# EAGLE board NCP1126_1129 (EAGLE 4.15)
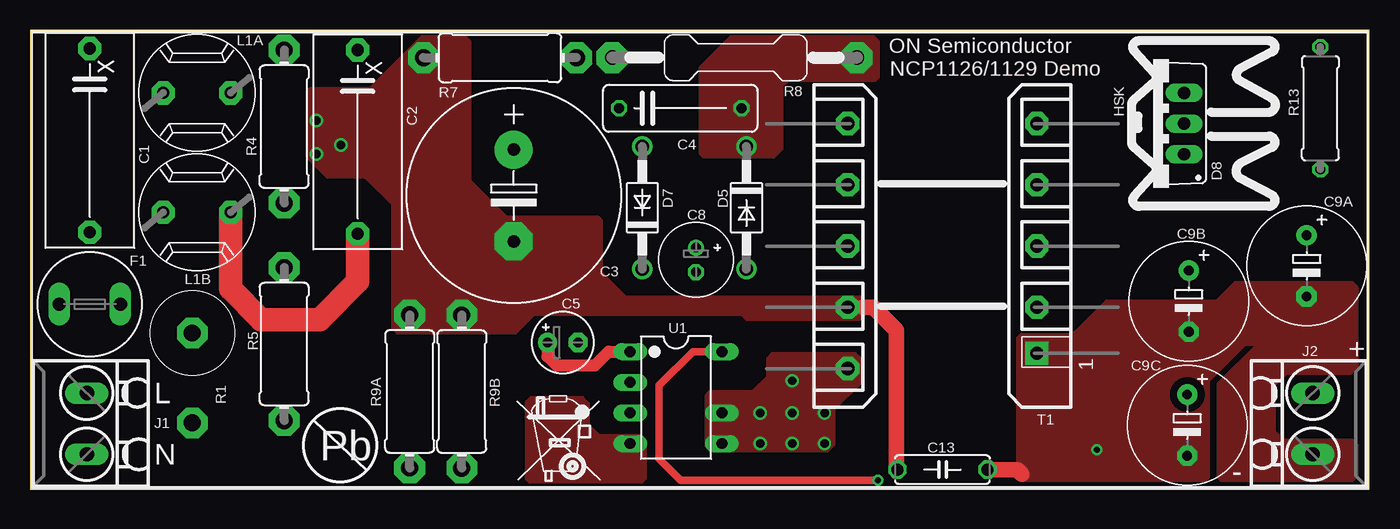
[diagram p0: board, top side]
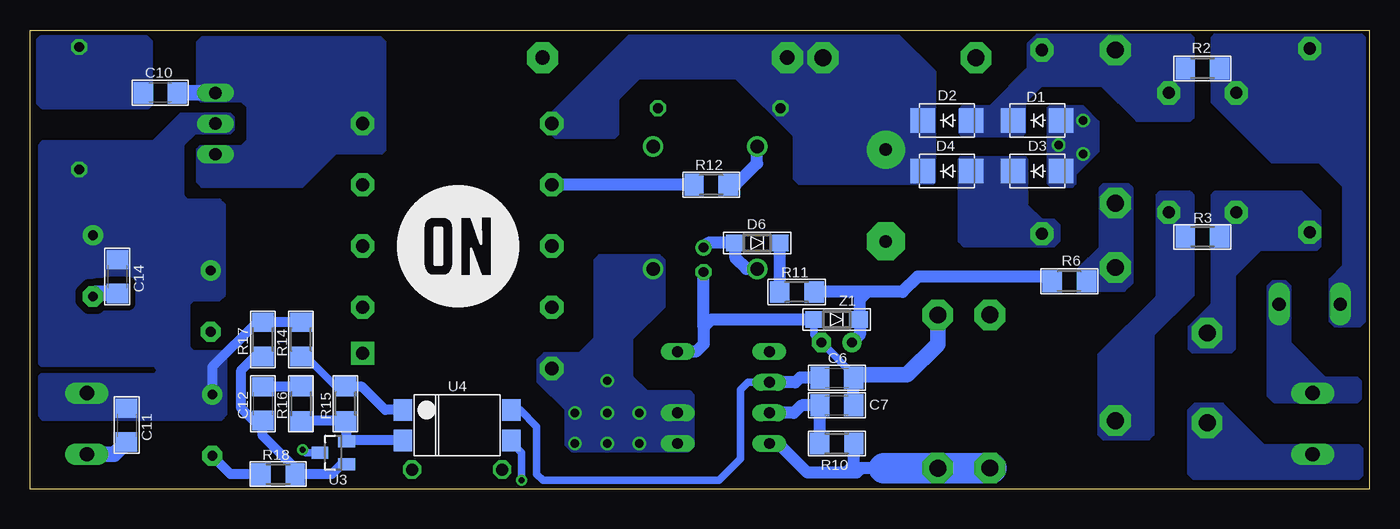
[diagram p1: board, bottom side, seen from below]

Size 111.13 x 38.1 mm. Coordinates in mm from the lower left corner, seen from the top.
Outline: 0,0 111.13,0 111.13,38.1 0,38.1 0,0
Copper layers (1*16): Top 0.035mm / dielectric 1.5mm / Bottom 0.035mm
Design rules "default": minimum track width 10mil, minimum drill 19mil, track to track 8mil, track to pad 8mil, pad to pad 8mil, via to via 8mil, smd to smd 8mil, copper to edge 10mil, drill to drill 8mil, minimum pad ring 10mil, minimum via ring 8mil, stop-mask expansion 4mil, vias tented up to drill 0mil, thermal gap 10mil

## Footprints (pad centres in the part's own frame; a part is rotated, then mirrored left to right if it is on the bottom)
XC18B7.5LS15 = drill 1.016 pad 1.93 octagon: 1 -7.62,0; 2 7.62,0
E7,5-18 = drill 1.016 pad 3.15 round: + -3.81,0 | drill 1.016 pad 3.15 octagon: - 3.81,0
C100-040X130 = drill 0.8 octagon: 1 -4.98,0; 2 5.18,0
E2,5-5 = drill 0.813 pad 1.6 round: + -1.27,0 | drill 0.813 pad 1.6 octagon: - 1.27,0
C1206 = smd 1.6 x 1.8: 1 -1.4,0; 2 1.4,0
E2-6.3 = drill 0.813 pad 1.27 round: + -1.016,0 | drill 0.813 pad 1.27 octagon: - 1.016,0
E5-10 = drill 0.8 pad 1.676 round: + -2.54,0 | drill 0.8 pad 1.676 octagon: - 2.54,0
C075-025X080 = drill 1 octagon: 1 -3.74,0; 2 3.74,0
SMA-DIODE = smd 2.032 x 2.032: A 1.994,0; C -1.994,0
DO41-10 = drill 1.118 round: A 5.08,0; C -5.08,0
SOD123 = smd 1.4 x 1.4: A 1.9,0; C -1.9,0
TO220ABS = drill 1.016 long: A1 -2.54,-2.54; A2 2.54,-2.54; C 0,-2.54
TR5 = drill 1.1 pad 1.778 long: 1 -2.54,0; 2 2.54,0
2-PIN = drill 1.2 long: + -2.54,0; - 2.54,0
RFB0810 = drill 1 pad 1.93 octagon: 1 -2.794,0; 2 2.794,0
3W-STAND-UP = drill 1.4 pad 2.54 octagon: P$1 3.75,0; P$2 -3.71,0
R1206 = smd 1.6 x 1.803: 1 -1.422,0; 2 1.422,0
0411/12 = drill 1.4 pad 2.54 octagon: 1 -6.35,0; 2 6.35,0
2W-DIA_4MM-LS_20MM = drill 1.2 pad 2.54 octagon: P$1 10.06,0; P$2 -10.26,0
0309/10 = drill 0.813 octagon: 1 -5.08,0; 2 5.08,0
E25/10/6-10P = drill 1.1 pad 1.93 square: 1 -8.89,-7.85 | drill 1.1 pad 1.93 octagon: 2 -5.08,-7.85; 3 0,-7.85; 4 5.08,-7.85; 5 10.16,-7.85; 6 10.16,7.85; 7 5.08,7.85; 8 0,7.85; 9 -5.08,7.85; 10 -10.16,7.85
DIP07_NO_PIN7 = drill 0.9 long: 1 -3.81,-3.81; 2 -1.27,-3.81; 3 1.27,-3.81; 4 3.81,-3.81; 5 3.81,3.81; 6 1.27,3.81; 8 -3.81,3.81
SOT-23 = smd 1 x 1.4: 1 -0.95,-1.1; 2 0.95,-1.1; 3 0,1.1
4PIN-SURFMOUNT-OPTO = smd 1.524 x 1.778: 1 4.496,-1.27; 2 4.496,1.27; 3 -4.496,1.27; 4 -4.496,-1.27

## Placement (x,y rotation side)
C1  0.1uF  [XC18B7.5LS15]  4.95,28.96 270 top
C2  0.1uF  [XC18B7.5LS15]  27.18,28.83 270 top
C3  47uF  [E7,5-18]  40.13,24.38 270 top
C4  10nF  [C100-040X130]  53.85,31.62 0 top
C5  4.7uF  [E2,5-5]  44.2,12.19 0 top
C6  1nF  [C1206]  44.2,9.27 0 bottom
C7  100pF  [C1206]  44.2,6.99 0 bottom
C8  22uF  [E2-6.3]  55.25,19.05 270 top
C9A  1000uF  [E5-10]  105.92,18.54 270 top
C9B  1000uF  [E5-10]  96.14,15.62 270 top
C9C  1000uF  [E5-10]  96.01,5.33 270 top
C10  0.1uF  [C1206]  100.33,32.89 180 bottom
C11  0.1uF  [C1206]  103.12,5.33 270 bottom
C12  0.1uF  [C1206]  91.82,7.11 270 bottom
C13  1nF  [C075-025X080]  75.69,1.65 0 top
C14  0.1uF  [C1206]  103.89,17.65 270 bottom
D1  MRA4007  [SMA-DIODE]  27.56,30.61 0 bottom
D2  MRA4007  [SMA-DIODE]  35.05,30.61 0 bottom
D3  MRA4007  [SMA-DIODE]  27.56,26.42 0 bottom
D4  MRA4007  [SMA-DIODE]  35.05,26.42 0 bottom
D5  1N4937  [DO41-10]  59.44,23.37 270 top
D6  MMSD4148A  [SOD123]  50.8,20.45 180 bottom
D7  1N4937  [DO41-10]  50.8,23.37 90 top
D8  MBR10H100CTG  [TO220ABS]  93.22,30.35 90 top
E$2  [ON2]  75.63,20.18 0 bottom
F1  2A/250Vac  [TR5]  4.95,15.37 180 top
HSK  [AAVID-576802B00000G]  99.19,30.35 90 top
J1  [2-PIN]  4.7,5.46 270 top
J2  [2-PIN]  106.43,5.46 90 top
L1A  820uH  [RFB0810]  13.84,32.89 0 top
L1B  820uH  [RFB0810]  13.84,22.99 0 top
R1  4.7/3W  [3W-STAND-UP]  13.46,9.27 270 top
R2  5.6K  [R1206]  13.84,34.93 0 bottom
R3  5.6K  [R1206]  13.84,20.96 0 bottom
R4  1M  [0411/12]  21.08,30.1 90 top
R5  1M  [0411/12]  21.08,12.07 90 top
R6  510K  [R1206]  24.89,17.27 0 bottom
R7  3M  [0411/12]  38.99,35.81 0 top
R8  47K  [2W-DIA_4MM-LS_20MM]  58.55,35.81 0 top
R9A  1/0.5W  [0411/12]  31.49,8.13 270 top
R9B  1/0.5W  [0411/12]  35.82,8.13 270 top
R10  2.4K  [R1206]  44.2,3.81 180 bottom
R11  0  [R1206]  47.5,16.38 0 bottom
R12  2.0  [R1206]  54.61,25.27 0 bottom
R13  33  [0309/10]  107.06,31.62 270 top
R14  1K  [R1206]  88.65,12.45 270 bottom
R15  15K  [R1206]  84.96,7.11 270 bottom
R16  20K  [R1206]  88.65,7.11 90 bottom
R17  39K  [R1206]  91.82,12.45 270 bottom
R18  10K  [R1206]  90.55,1.27 180 bottom
T1  [E25/10/6-10P]  75.69,20.19 90 top
U1  NCP1129  [DIP07_NO_PIN7]  53.59,7.62 270 top
U3  NCP431A  [SOT-23]  85.98,3.05 90 bottom
U4  PS2561L_1  [4PIN-SURFMOUNT-OPTO]  75.69,5.33 180 bottom
U$3  [WEEE_SMALL]  44,2.02 0 top
Z1  MMSZ5253B  [SOD123]  44.2,14.1 180 bottom

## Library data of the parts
C1-C8 C9A C9B C9C C10-C14 R2-R7 R9A R9B R10-R18 = rcl
D1-D8 Z1 = diode
E$2 = loga
F1 = fuse
HSK = heatsink
J1 J2 = My CONNECTOR lib
L1A L1B = MY  INDUCTOR Lib
R1 R8 = resistor-power
T1 = My X-former
U1 U3 = My IC Lib
U4 = optocoupler
U$3 = My Sign Lib

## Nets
N$1: C1.1 F1.2 L1A.1 R2.2
N$2: J1.- R1.P$1
N$3: C2.1 D1.C D2.A L1A.2 R2.1 R4.2
N$4: C1.2 L1B.1 R1.P$2 R3.2
N$5: F1.1 J1.+
N$6: C2.2 D3.C D4.A L1B.2 R3.1 R5.1
N$7: C5.+ R6.1 R11.2 U1.1 Z1.C
N$8: C4.2 D5.C R8.P$1
N$9: D5.A T1.10 U1.5 U1.6
N$10: C3.+ C4.1 D2.C D4.C R7.2 R8.P$2 T1.6
N$11: C6.1 U1.2 U4.4
N$12: R12.1 T1.7
N$13: R9A.2 R9B.2 R10.1 U1.4
N$14: C3.- C5.- C6.2 C7.2 C8.- C13.1 D1.A D3.A R7.1 R9A.1 R9B.1 T1.9 U1.8 U4.3 Z1.A
N$15: C7.1 R10.2 U1.3
N$16: D7.A R12.2
N$17: C9A.+ C9B.+ C9C.+ C11.1 C14.1 D8.C J2.- R13.2 R14.1 R17.1
N$18: R4.1 R5.2 R6.2
N$19: C9A.- C9B.- C9C.- C11.2 C13.2 C14.2 J2.+ R18.2 T1.1 U3.3
N$21: R14.2 R15.1 U4.1
N$22: C8.+ D6.A D7.C
N$23: R15.2 R16.1 U3.2 U4.2
N$24: C10.2 R13.1
N$25: C12.1 R16.2
N$26: C12.2 R17.2 R18.1 U3.1
N$27: C10.1 D8.A1 D8.A2 T1.5
N$28: D6.C R11.1

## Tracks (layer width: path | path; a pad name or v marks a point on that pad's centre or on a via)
N$1
  pour Bottom (no thermals): 0.38,13.97 0.38,37.47 0.64,37.72 12.83,37.72 13.08,37.47 13.08,32.13 8.13,27.18 4.19,27.18 2.16,25.15 2.16,18.54 3.3,17.4 3.3,13.97 2.92,13.59 0.76,13.59
N$2
  pour Bottom (no thermals): 0.89,0.89 14.61,0.89 14.99,1.27 14.99,6.6 14.48,7.11 12.19,7.11 8.76,3.68 0.89,3.68 0.64,3.43 0.64,1.14
N$3
  pour Bottom (no thermals): 14.61,30.86 14.61,37.47 14.86,37.72 27.56,37.72 28.32,36.96 28.32,34.93 31.5,31.75 33.78,31.75 34.04,31.5 34.04,29.59 33.78,29.34 28.83,29.34 28.58,29.59 28.58,32.13 27.18,33.53 22.23,33.53 19.3,30.61 14.86,30.61
N$4
  pour Bottom (no thermals): 4.06,23.11 5.59,24.64 12.83,24.64 13.08,24.38 13.08,15.37 14.99,13.46 14.99,11.68 14.73,11.43 11.43,11.43 11.18,11.68 11.18,17.78 9.02,19.94 4.32,19.94 4.06,20.19
N$5
  pour Bottom (no thermals): 1.02,7.24 7.87,7.24 8.38,7.75 8.38,16.89 8,17.27 6.99,17.27 6.6,16.89 6.6,12.19 3.68,9.27 1.02,9.27 0.76,9.02 0.76,7.49
N$6
  Top 1.93: L1B.2 16.64,16.64 19.18,14.1 24,14.1 27.18,17.27 C2.2
  pour Bottom (no thermals): 17.91,4.57 17.91,12.83 14.61,16.13 14.61,24.38 14.86,24.64 17.4,24.64 17.65,24.38 17.65,16 22.48,11.18 22.48,4.57 22.1,4.19 18.29,4.19
  pour Bottom (no thermals): 26.16,20.19 33.66,20.19 34.04,20.57 34.04,27.43 33.91,27.56 28.58,27.56 28.45,27.43 28.45,23.62 27.18,22.35 26.16,22.35 25.78,21.97 25.78,20.57
N$7
  Top 1.016: U1.1 48.01,11.43 46.86,10.29 43.69,10.29 42.93,11.05 C5.+
  Bottom 1.016: R6.1 26.31,17.3 26.67,17.65 37.47,17.65 38.74,16.38 41.66,16.38 | 41.66,16.38 R11.2 | 41.66,16.38 42.3,15.74 Z1.C 42.29,12.83 C5.+
N$8
  pour Top (no thermals): 55.63,27.81 55.63,35.05 58.17,37.59 69.98,37.59 70.36,37.21 70.36,34.16 70.1,33.91 62.87,33.91 62.36,33.4 62.36,28.19 61.72,27.56 55.88,27.56
N$9  (via drill 0.7)
  other vias: 63.25,6.35 65.91,6.35 65.91,3.81 63.25,9.02 60.58,6.35 60.58,3.81 63.25,3.81
  pour Bottom (no thermals): 56.52,3.18 66.17,3.18 66.68,3.68 66.68,6.6 68.96,8.89 68.96,10.8 68.45,11.3 65.53,11.3 64.26,12.57 64.26,19.05 63.88,19.43 58.93,19.43 58.55,19.05 58.55,15.11 61.21,12.45 61.21,9.4 59.94,8.13 56.39,8.13 56.13,7.87 56.13,3.56
  pour Top (no thermals): 56.39,8.13 59.94,8.13 61.21,9.4 61.21,10.92 61.6,11.3 68.45,11.3 68.96,10.8 68.96,8.89 66.68,6.6 66.68,3.68 66.17,3.18 56.52,3.18 56.13,3.56 56.13,7.87
N$10
  pour Bottom (no thermals): 36.07,25.53 36.07,34.67 38.99,37.59 61.47,37.59 67.95,31.12 67.95,29.59 67.56,29.21 62.61,29.21 62.36,29.46 62.36,32.39 60.58,34.16 52.58,34.16 47.75,29.34 47.75,25.78 47.37,25.4 36.2,25.4
N$11
  Bottom 0.61: U4.4 70.49,6.6 69.09,5.21 69.09,1.27 68.58,0.76 53.98,0.76 52.2,2.54 52.2,8.26 51.56,8.89 U1.2
  Bottom 1.016: C6.1 47.24,9.27 47.63,8.89 U1.2
N$12
  Bottom 1.016: 56.01,25.27 R12.1 T1.7 67.95,25.27 | 56.01,25.27
N$13
  Bottom 1.016: U1.4 49.02,3.81 46.61,1.4 43.43,1.4 | 40.26,1.78 42.16,1.78 42.55,1.4 43.43,1.4 | R10.1 42.77,2.06 43.43,1.4
  Bottom 2.54: 35.69,1.78 R9B.2 | 35.69,1.78 40.26,1.78 | R9A.2 31.37,1.78 35.69,1.78
  pour Top (no thermals): 50.67,4.45 47.24,4.45 46.36,5.33 46.36,7.11 45.85,7.62 41.53,7.62 41.15,7.24 41.15,0.89 41.4,0.64 50.8,0.64 51.05,0.89 51.05,4.06
N$14  (via drill 0.5, 0.7)
  Top 0.61: v70.36,0.76 53.98,0.76 52.2,2.54 52.2,8.64 54.99,11.43 U1.8
  Top 1.016: 67.82,15.11 T1.9 69.09,15.11
  Top 1.27: C13.1 71.88,1.65 71.88,13.21 69.98,15.11 69.09,15.11
  Bottom 0.61: C6.2 42.8,9.52 C5.- 46.1,12.83 46.1,13.97 46.1,13.98 Z1.A | U4.3 71.2,3.89 70.36,3.05 v70.36,0.76
  Bottom 1.016: C7.2 42.8,7.11 42.8,7.12 C6.2 | 55.25,13.46 C8.- | 55.25,13.46 55.25,12.07 55.88,11.43 U1.8 | Z1.A 54.61,14.1 55.25,13.46
  Bottom 1.27: 42.8,9.52 38.36,9.52 35.81,12.07 R9B.1
  other vias: 25.78,28.58 23.75,30.61 23.75,27.81
  pour Bottom (no thermals): 26.42,25.15 24.64,25.15 24.38,25.4 24.38,26.16 22.48,28.07 22.48,30.48 23.75,31.75 26.54,31.75 26.67,31.62 26.67,25.4
  pour Top (no thermals): 68.83,16 69.34,15.49 69.34,14.61 68.83,14.1 59.44,14.1 59.06,14.48 41.78,14.48 40.26,12.95 30.48,12.95 30.1,13.34 30.1,23.62 27.81,25.91 24.64,25.91 22.99,27.56 22.99,33.02 23.24,33.27 28.19,33.27 32.51,37.59 36.07,37.59 36.45,37.21 36.45,25.65 39.5,22.61 47.12,22.61 47.37,22.35 47.37,18.03 49.4,16
N$15
  Bottom 1.016: U1.3 47.75,6.35 47.12,6.99 C7.1 45.6,3.81 45.59,3.81 R10.2
N$16
  Bottom 1.016: D7.A 50.8,27.05 52.58,25.27 R12.2
N$17
  Bottom 0.813: R14.1 91.8,13.87 91.82,13.84 R17.1 92.3,13.87 96.01,10.16 C9C.+
  pour Bottom (isolate 0.61, no thermals): 94.49,31.12 98.68,31.12 100.97,28.83 110.11,28.83 110.49,28.45 110.49,10.54 110.24,10.29 100.84,10.29 100.58,10.03 100.58,9.78 100.84,9.53 110.24,9.53 110.49,9.27 110.49,6.22 110.11,5.84 95.25,5.84 94.87,6.22 94.87,11.05 95.25,11.43 97.54,11.43 97.92,11.81 97.92,15.37 97.54,15.75 95.38,15.75 95,16.13 95,23.62 95.38,24 98.04,24 98.43,24.38 98.43,28.58 97.41,29.59 94.49,29.59 94.23,29.85 94.23,30.86
N$18
  pour Bottom (no thermals): 19.69,17.15 19.69,25.02 19.94,25.27 22.1,25.27 22.35,25.02 22.35,20.07 24.13,18.29 24.13,16.76 23.88,16.51 20.32,16.51
N$19  (via drill 0.5)
  Top 1.27: C13.2 81.92,1.65 82.3,1.27
  Bottom 0.61: U3.3 88.27,3.05 v88.52,3.3
  Bottom 0.813: U3.3 87.12,3.05 | R18.2 94.49,1.27 C9C.-
  Bottom 1.27: C9A.- 105.66,16.26 C14.2 | C11.2 104.14,2.92 J2.+
  pour Top (isolate 0.61, no thermals): 109.73,17.15 99.95,17.15 98.43,15.62 89.28,15.62 86.49,12.83 82.17,12.83 81.92,12.57 81.92,1.14 82.3,0.76 97.54,0.76 97.79,1.02 97.79,9.02 100.84,12.07 101.85,12.07 98.55,8.76 98.55,1.02 98.81,0.76 109.73,0.76 110.11,1.14 110.11,3.68 109.73,4.06 104.01,4.06 103.25,4.83 103.25,8.64 104.27,9.65 109.6,9.65 110.11,10.16 110.11,16.76
N$21
  Bottom 0.61: R14.2 88.29,11.02 88.27,11.05 85.75,8.53 R15.1
  Bottom 0.813: U4.1 81.66,6.6 83.57,8.51 84.96,8.51 R15.1
N$22
  Bottom 1.016: C8.+ 54.86,20.45 D6.A | D7.C 51.69,18.29 52.58,19.18 52.58,20.32 D6.A | D6.A
N$23
  Bottom 0.61: 84.84,4.06 84.88,4.02 U3.2
  Bottom 0.813: U4.2 84.84,4.06 | U3.2 84.88,5.5 84.96,5.59 R15.2 88.62,5.69 88.65,5.72 R16.1
N$24
  pour Bottom (no thermals): 101.35,31.62 110.11,31.62 110.49,32 110.49,37.34 110.24,37.59 101.47,37.59 101.09,37.21 101.09,31.88
N$25
  Bottom 0.813: C12.1 91.8,8.53 R16.2
N$26
  Bottom 0.813: U3.1 85.28,2.1 86.11,1.27 R18.1 89.13,1.75 91.82,4.45 C12.2 | R17.2 92.48,11.02 93.6,9.91 93.6,6.73 92.58,5.72 C12.2 | C12.2
N$27
  Bottom 1.27: C10.1 D8.A2
  pour Bottom (no thermals): 81.66,28.19 81.66,37.08 82.04,37.47 96.9,37.47 97.28,37.08 97.28,32.51 97.03,32.26 93.6,32.26 93.09,31.75 93.09,28.96 93.6,28.45 97.03,28.45 97.28,28.19 97.28,25.53 96.9,25.15 88.52,25.15 85.73,27.94 81.92,27.94
N$28
  Bottom 1.016: D6.C 48.9,20.33 48.9,20.32 48.92,20.3 R11.1

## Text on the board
tPlace: ON Semiconductor | NCP1126/1129 Demo | + | L | Pb | N | -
